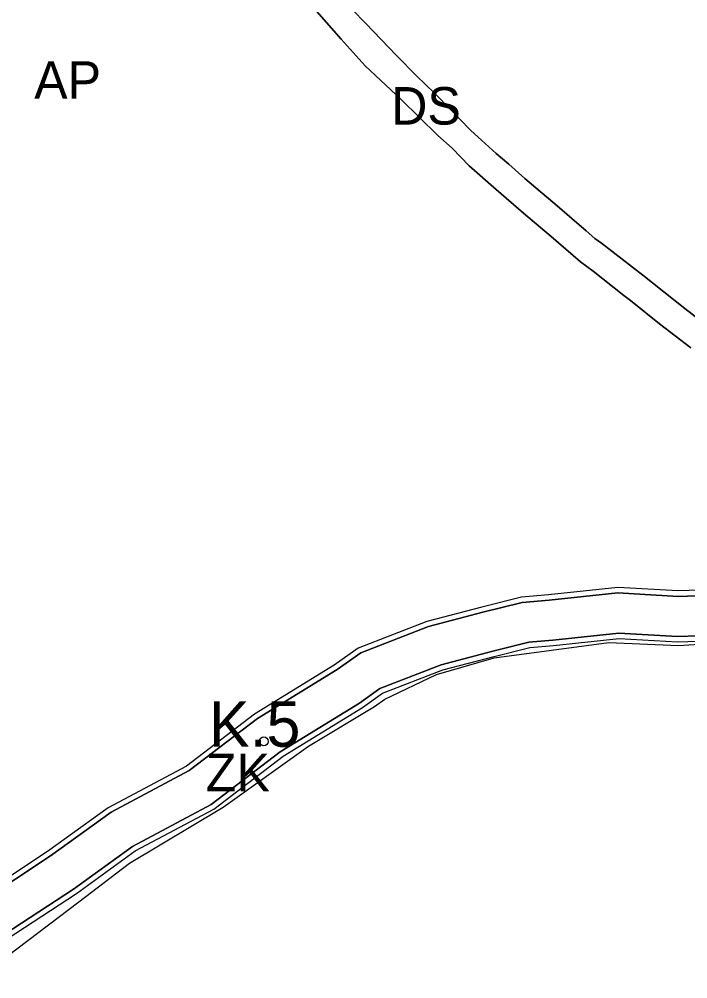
# Model space of a CAD drawing. Extents: x -555509 to -553005, y -1186756 to -1182560.
# Drawn here: x -553505.6 to -553255.9, y -1186166.6 to -1185808.2 of the extents above; entities that cross this region are included whole.
import ezdxf

# ---------------------------------------------------------------- set-up
doc = ezdxf.new("R2010")
doc.units = 0
for name, color, linetype in [('Level 26', 7, 'Continuous'), ('Level 46', 7, 'Continuous'), ('Level 56', 7, 'Continuous'), ('Level 59', 7, 'Continuous'), ('Level 63', 7, 'Continuous'), ('navrh_ZK', 7, 'Continuous'), ('OBRYS_PLOCH', 7, 'Continuous'), ('stav_AP', 7, 'Continuous'), ('stav_DS', 7, 'Continuous')]:
    doc.layers.add(name, color=color, linetype=linetype)

msp = doc.modelspace()

# ---------------------------------------------------------------- linework, layer by layer
at = {"layer": 'Level 26'}
for p, q in [((-553306.3, -1186040.1), (-553315.27, -1186040.84)), ((-553281.66, -1186037.48), (-553306.3, -1186040.1)), ((-553259.77, -1186038.75), (-553281.66, -1186037.48)), ((-553237.04, -1186038), (-553259.77, -1186038.75)), ((-553315.27, -1186040.84), (-553328.68, -1186044.22)), ((-553328.28, -1186046.67), (-553285.47, -1186040.94)), ((-553285.47, -1186040.94), (-553259.44, -1186042.1)), ((-553259.44, -1186042.1), (-553232.89, -1186040.35)), ((-553349.78, -1186052.91), (-553328.28, -1186046.67)), ((-553328.68, -1186044.22), (-553348.08, -1186049.28)), ((-553348.08, -1186049.28), (-553370.87, -1186058.18)), ((-553369.03, -1186062.12), (-553349.78, -1186052.91)), ((-553370.87, -1186058.18), (-553378.55, -1186063.63)), ((-553378.55, -1186063.63), (-553408.08, -1186081.8)), ((-553397.54, -1186079.66), (-553372.88, -1186064.84)), ((-553372.88, -1186064.84), (-553369.03, -1186062.12)), ((-553429.45, -1186102.43), (-553397.54, -1186079.66)), ((-553408.08, -1186081.8), (-553433.95, -1186101.46)), ((-553464.42, -1186123.36), (-553429.45, -1186102.43)), ((-553433.95, -1186101.46), (-553463.3, -1186117.12)), ((-553463.3, -1186117.12), (-553485.32, -1186133.04)), ((-553483.34, -1186137.78), (-553464.42, -1186123.36)), ((-553485.32, -1186133.04), (-553511.19, -1186150.03)), ((-553521.16, -1186166.55), (-553483.34, -1186137.78))]:
    msp.add_line(p, q, dxfattribs=at)
at = {"layer": 'Level 46'}
msp.add_circle((-553414.23, -1186077.88), 1.64, dxfattribs=at)
at = {"layer": 'Level 56'}
for points in [[(-553239.12, -1186021.06), (-553259.56, -1186021.73), (-553282.07, -1186020.43), (-553307.9, -1186023.17), (-553318.06, -1186024.01), (-553332.9, -1186027.75), (-553353.34, -1186033.08), (-553379, -1186043.11), (-553387.93, -1186049.44), (-553417.7, -1186067.76), (-553443.15, -1186087.1), (-553472.32, -1186102.67), (-553494.97, -1186119.04), (-553521, -1186136.13)], [(-553510.04, -1186151.66), (-553484.18, -1186134.69), (-553462.24, -1186118.82), (-553432.87, -1186103.15), (-553406.95, -1186083.45), (-553377.45, -1186065.3), (-553369.91, -1186059.95), (-553347.46, -1186051.19), (-553328.18, -1186046.16), (-553314.94, -1186042.82), (-553306.11, -1186042.09), (-553281.61, -1186039.49), (-553259.79, -1186040.75), (-553236.8, -1186039.99)]]:
    msp.add_lwpolyline(points, dxfattribs=at)
at = {"layer": 'navrh_ZK'}
for points in [[(-553238.87, -1186023.05), (-553259.58, -1186023.74), (-553282.02, -1186022.43), (-553307.71, -1186025.17), (-553317.74, -1186025.99), (-553332.41, -1186029.69), (-553352.72, -1186034.99), (-553378.05, -1186044.88), (-553386.83, -1186051.11), (-553416.57, -1186069.41), (-553442.07, -1186088.79), (-553471.26, -1186104.37), (-553493.84, -1186120.69), (-553519.85, -1186137.77)], [(-553511.19, -1186150.03), (-553485.32, -1186133.04), (-553463.3, -1186117.12), (-553433.95, -1186101.46), (-553408.08, -1186081.8), (-553378.55, -1186063.63), (-553370.87, -1186058.18), (-553348.08, -1186049.28), (-553328.68, -1186044.22), (-553315.27, -1186040.84), (-553306.3, -1186040.1), (-553281.66, -1186037.48), (-553259.77, -1186038.75), (-553237.04, -1186038)]]:
    msp.add_lwpolyline(points, dxfattribs=at)
at = {"layer": 'OBRYS_PLOCH'}
for p, q in [((-553402.77, -1185795.87), (-553385.33, -1185815.75)), ((-553385.33, -1185815.75), (-553402.77, -1185795.87)), ((-553385.33, -1185815.75), (-553402.77, -1185795.87)), ((-553381.11, -1185804.72), (-553376.26, -1185809.74)), ((-553376.26, -1185809.74), (-553381.11, -1185804.72)), ((-553376.26, -1185809.74), (-553370.42, -1185815.8)), ((-553370.42, -1185815.8), (-553376.26, -1185809.74)), ((-553385.33, -1185815.75), (-553376.38, -1185825.65)), ((-553376.38, -1185825.65), (-553385.33, -1185815.75)), ((-553376.38, -1185825.65), (-553385.33, -1185815.75)), ((-553370.42, -1185815.8), (-553364.57, -1185821.89)), ((-553364.57, -1185821.89), (-553370.42, -1185815.8)), ((-553364.57, -1185821.89), (-553357.23, -1185829.41)), ((-553357.23, -1185829.41), (-553364.57, -1185821.89)), ((-553376.38, -1185825.65), (-553362.96, -1185838.27)), ((-553362.96, -1185838.27), (-553376.38, -1185825.65)), ((-553362.96, -1185838.27), (-553376.38, -1185825.65)), ((-553357.23, -1185829.41), (-553350.57, -1185835.89)), ((-553350.57, -1185835.89), (-553357.23, -1185829.41)), ((-553350.57, -1185835.89), (-553344.21, -1185842.36)), ((-553344.21, -1185842.36), (-553350.57, -1185835.89)), ((-553362.96, -1185838.27), (-553349.22, -1185851.67)), ((-553349.22, -1185851.67), (-553362.96, -1185838.27)), ((-553349.22, -1185851.67), (-553362.96, -1185838.27)), ((-553344.21, -1185842.36), (-553337.49, -1185849.32)), ((-553337.49, -1185849.32), (-553344.21, -1185842.36)), ((-553337.49, -1185849.32), (-553337.01, -1185849.82)), ((-553337.01, -1185849.82), (-553337.49, -1185849.32)), ((-553337.01, -1185849.82), (-553332.98, -1185853.45)), ((-553332.98, -1185853.45), (-553337.01, -1185849.82)), ((-553349.22, -1185851.67), (-553343.93, -1185856.35)), ((-553343.93, -1185856.35), (-553349.22, -1185851.67)), ((-553343.93, -1185856.35), (-553349.22, -1185851.67)), ((-553332.98, -1185853.45), (-553327.51, -1185858.37)), ((-553327.51, -1185858.37), (-553332.98, -1185853.45)), ((-553343.93, -1185856.35), (-553337.6, -1185862.96)), ((-553337.6, -1185862.96), (-553343.93, -1185856.35)), ((-553337.6, -1185862.96), (-553343.93, -1185856.35)), ((-553327.51, -1185858.37), (-553322.77, -1185862.39)), ((-553322.77, -1185862.39), (-553327.51, -1185858.37)), ((-553337.6, -1185862.96), (-553327.44, -1185871.78)), ((-553327.44, -1185871.78), (-553337.6, -1185862.96)), ((-553327.44, -1185871.78), (-553337.6, -1185862.96)), ((-553322.77, -1185862.39), (-553316.74, -1185867.67)), ((-553316.74, -1185867.67), (-553322.77, -1185862.39)), ((-553316.74, -1185867.67), (-553311.01, -1185872.54)), ((-553311.01, -1185872.54), (-553316.74, -1185867.67)), ((-553327.44, -1185871.78), (-553317.23, -1185880.63)), ((-553317.23, -1185880.63), (-553327.44, -1185871.78)), ((-553317.23, -1185880.63), (-553327.44, -1185871.78)), ((-553311.01, -1185872.54), (-553305.6, -1185877.13)), ((-553305.6, -1185877.13), (-553311.01, -1185872.54)), ((-553305.6, -1185877.13), (-553299.29, -1185882.62)), ((-553299.29, -1185882.62), (-553305.6, -1185877.13)), ((-553317.23, -1185880.63), (-553306.92, -1185889.37)), ((-553306.92, -1185889.37), (-553317.23, -1185880.63)), ((-553306.92, -1185889.37), (-553317.23, -1185880.63)), ((-553299.29, -1185882.62), (-553293.85, -1185887.3)), ((-553293.85, -1185887.3), (-553299.29, -1185882.62)), ((-553306.92, -1185889.37), (-553295.97, -1185898.84)), ((-553295.97, -1185898.84), (-553306.92, -1185889.37)), ((-553295.97, -1185898.84), (-553306.92, -1185889.37)), ((-553293.85, -1185887.3), (-553290.71, -1185890.11)), ((-553290.71, -1185890.11), (-553293.85, -1185887.3)), ((-553290.71, -1185890.11), (-553288.2, -1185891.84)), ((-553288.2, -1185891.84), (-553290.71, -1185890.11)), ((-553288.2, -1185891.84), (-553272.75, -1185903.87)), ((-553272.75, -1185903.87), (-553288.2, -1185891.84)), ((-553295.97, -1185898.84), (-553291.3, -1185902.33)), ((-553291.3, -1185902.33), (-553295.97, -1185898.84)), ((-553291.3, -1185902.33), (-553295.97, -1185898.84)), ((-553291.3, -1185902.33), (-553279.88, -1185911.4)), ((-553279.88, -1185911.4), (-553291.3, -1185902.33)), ((-553279.88, -1185911.4), (-553291.3, -1185902.33)), ((-553272.75, -1185903.87), (-553257.04, -1185916.2)), ((-553257.04, -1185916.2), (-553272.75, -1185903.87)), ((-553279.88, -1185911.4), (-553277.29, -1185913.25)), ((-553277.29, -1185913.25), (-553279.88, -1185911.4)), ((-553277.29, -1185913.25), (-553279.88, -1185911.4)), ((-553277.29, -1185913.25), (-553266.45, -1185922.03)), ((-553266.45, -1185922.03), (-553277.29, -1185913.25)), ((-553266.45, -1185922.03), (-553277.29, -1185913.25)), ((-553257.04, -1185916.2), (-553241.32, -1185928.48)), ((-553241.32, -1185928.48), (-553257.04, -1185916.2)), ((-553266.45, -1185922.03), (-553254.85, -1185930.89)), ((-553254.85, -1185930.89), (-553266.45, -1185922.03)), ((-553254.85, -1185930.89), (-553266.45, -1185922.03)), ((-553317.74, -1186025.99), (-553307.71, -1186025.17)), ((-553307.71, -1186025.17), (-553282.02, -1186022.43)), ((-553282.02, -1186022.43), (-553259.58, -1186023.74)), ((-553259.58, -1186023.74), (-553238.87, -1186023.05)), ((-553378.05, -1186044.88), (-553352.72, -1186034.99)), ((-553306.3, -1186040.1), (-553315.27, -1186040.84)), ((-553281.66, -1186037.48), (-553306.3, -1186040.1)), ((-553259.77, -1186038.75), (-553281.66, -1186037.48)), ((-553237.04, -1186038), (-553259.77, -1186038.75)), ((-553315.27, -1186040.84), (-553328.68, -1186044.22)), ((-553328.28, -1186046.67), (-553285.47, -1186040.94)), ((-553285.47, -1186040.94), (-553259.44, -1186042.1)), ((-553259.44, -1186042.1), (-553232.89, -1186040.35)), ((-553386.83, -1186051.11), (-553378.05, -1186044.88)), ((-553349.78, -1186052.91), (-553328.28, -1186046.67)), ((-553328.68, -1186044.22), (-553348.08, -1186049.28)), ((-553348.08, -1186049.28), (-553370.87, -1186058.18)), ((-553416.57, -1186069.41), (-553386.83, -1186051.11)), ((-553369.03, -1186062.12), (-553349.78, -1186052.91)), ((-553370.87, -1186058.18), (-553378.55, -1186063.63)), ((-553378.55, -1186063.63), (-553408.08, -1186081.8)), ((-553397.54, -1186079.66), (-553372.88, -1186064.84)), ((-553372.88, -1186064.84), (-553369.03, -1186062.12)), ((-553429.45, -1186102.43), (-553397.54, -1186079.66)), ((-553408.08, -1186081.8), (-553433.95, -1186101.46)), ((-553471.26, -1186104.37), (-553442.07, -1186088.79)), ((-553493.84, -1186120.69), (-553471.26, -1186104.37)), ((-553464.42, -1186123.36), (-553429.45, -1186102.43)), ((-553433.95, -1186101.46), (-553463.3, -1186117.12)), ((-553463.3, -1186117.12), (-553485.32, -1186133.04)), ((-553519.85, -1186137.77), (-553493.84, -1186120.69)), ((-553483.34, -1186137.78), (-553464.42, -1186123.36)), ((-553485.32, -1186133.04), (-553511.19, -1186150.03)), ((-553521.16, -1186166.55), (-553483.34, -1186137.78))]:
    msp.add_line(p, q, dxfattribs=at)
for points in [[(-553307.71, -1186025.17), (-553282.02, -1186022.43), (-553259.58, -1186023.74), (-553238.87, -1186023.05), (-553235.04, -1186022.23), (-553222.52, -1186019.49)], [(-553238.87, -1186023.05), (-553259.58, -1186023.74), (-553282.02, -1186022.43), (-553307.71, -1186025.17), (-553317.74, -1186025.99), (-553332.41, -1186029.69), (-553352.72, -1186034.99), (-553378.05, -1186044.88), (-553386.83, -1186051.11), (-553416.57, -1186069.41), (-553442.07, -1186088.79), (-553471.26, -1186104.37), (-553493.84, -1186120.69), (-553519.85, -1186137.77)], [(-553332.41, -1186029.69), (-553317.74, -1186025.99), (-553307.71, -1186025.17)], [(-553352.72, -1186034.99), (-553332.41, -1186029.69), (-553317.74, -1186025.99)], [(-553378.05, -1186044.88), (-553352.72, -1186034.99), (-553332.41, -1186029.69)], [(-553511.19, -1186150.03), (-553485.32, -1186133.04), (-553463.3, -1186117.12), (-553433.95, -1186101.46), (-553408.08, -1186081.8), (-553378.55, -1186063.63), (-553370.87, -1186058.18), (-553348.08, -1186049.28), (-553328.68, -1186044.22), (-553315.27, -1186040.84), (-553306.3, -1186040.1), (-553281.66, -1186037.48), (-553259.77, -1186038.75), (-553237.04, -1186038)], [(-553442.07, -1186088.79), (-553416.57, -1186069.41), (-553386.83, -1186051.11), (-553378.05, -1186044.88)], [(-553535.86, -1186150.36), (-553531.2, -1186146.37), (-553519.85, -1186137.77), (-553493.84, -1186120.69), (-553471.26, -1186104.37), (-553442.07, -1186088.79), (-553416.57, -1186069.41)]]:
    msp.add_lwpolyline(points, dxfattribs=at)
at = {"layer": 'stav_AP'}
for p, q in [((-553385.33, -1185815.75), (-553402.77, -1185795.87)), ((-553381.11, -1185804.72), (-553376.26, -1185809.74)), ((-553376.26, -1185809.74), (-553370.42, -1185815.8)), ((-553376.38, -1185825.65), (-553385.33, -1185815.75)), ((-553370.42, -1185815.8), (-553364.57, -1185821.89)), ((-553364.57, -1185821.89), (-553357.23, -1185829.41)), ((-553362.96, -1185838.27), (-553376.38, -1185825.65)), ((-553357.23, -1185829.41), (-553350.57, -1185835.89)), ((-553350.57, -1185835.89), (-553344.21, -1185842.36)), ((-553349.22, -1185851.67), (-553362.96, -1185838.27)), ((-553344.21, -1185842.36), (-553337.49, -1185849.32)), ((-553337.49, -1185849.32), (-553337.01, -1185849.82)), ((-553337.01, -1185849.82), (-553332.98, -1185853.45)), ((-553343.93, -1185856.35), (-553349.22, -1185851.67)), ((-553332.98, -1185853.45), (-553327.51, -1185858.37)), ((-553337.6, -1185862.96), (-553343.93, -1185856.35)), ((-553327.51, -1185858.37), (-553322.77, -1185862.39)), ((-553327.44, -1185871.78), (-553337.6, -1185862.96)), ((-553322.77, -1185862.39), (-553316.74, -1185867.67)), ((-553316.74, -1185867.67), (-553311.01, -1185872.54)), ((-553317.23, -1185880.63), (-553327.44, -1185871.78)), ((-553311.01, -1185872.54), (-553305.6, -1185877.13)), ((-553305.6, -1185877.13), (-553299.29, -1185882.62)), ((-553306.92, -1185889.37), (-553317.23, -1185880.63)), ((-553299.29, -1185882.62), (-553293.85, -1185887.3)), ((-553295.97, -1185898.84), (-553306.92, -1185889.37)), ((-553293.85, -1185887.3), (-553290.71, -1185890.11)), ((-553290.71, -1185890.11), (-553288.2, -1185891.84)), ((-553288.2, -1185891.84), (-553272.75, -1185903.87)), ((-553291.3, -1185902.33), (-553295.97, -1185898.84)), ((-553279.88, -1185911.4), (-553291.3, -1185902.33)), ((-553272.75, -1185903.87), (-553257.04, -1185916.2)), ((-553277.29, -1185913.25), (-553279.88, -1185911.4)), ((-553266.45, -1185922.03), (-553277.29, -1185913.25)), ((-553257.04, -1185916.2), (-553241.32, -1185928.48)), ((-553254.85, -1185930.89), (-553266.45, -1185922.03)), ((-553317.74, -1186025.99), (-553307.71, -1186025.17)), ((-553259.58, -1186023.74), (-553238.87, -1186023.05)), ((-553378.05, -1186044.88), (-553352.72, -1186034.99)), ((-553442.07, -1186088.79), (-553416.57, -1186069.41)), ((-553519.85, -1186137.77), (-553493.84, -1186120.69))]:
    msp.add_line(p, q, dxfattribs=at)
for points in [[(-553307.71, -1186025.17), (-553282.02, -1186022.43), (-553259.58, -1186023.74)], [(-553352.72, -1186034.99), (-553332.41, -1186029.69), (-553317.74, -1186025.99)], [(-553416.57, -1186069.41), (-553386.83, -1186051.11), (-553378.05, -1186044.88)], [(-553493.84, -1186120.69), (-553471.26, -1186104.37), (-553442.07, -1186088.79)]]:
    msp.add_lwpolyline(points, dxfattribs=at)
at = {"layer": 'stav_DS'}
for p, q in [((-553402.77, -1185795.87), (-553385.33, -1185815.75)), ((-553376.26, -1185809.74), (-553381.11, -1185804.72)), ((-553370.42, -1185815.8), (-553376.26, -1185809.74)), ((-553385.33, -1185815.75), (-553376.38, -1185825.65)), ((-553364.57, -1185821.89), (-553370.42, -1185815.8)), ((-553357.23, -1185829.41), (-553364.57, -1185821.89)), ((-553376.38, -1185825.65), (-553362.96, -1185838.27)), ((-553350.57, -1185835.89), (-553357.23, -1185829.41)), ((-553344.21, -1185842.36), (-553350.57, -1185835.89)), ((-553362.96, -1185838.27), (-553349.22, -1185851.67)), ((-553337.49, -1185849.32), (-553344.21, -1185842.36)), ((-553337.01, -1185849.82), (-553337.49, -1185849.32)), ((-553332.98, -1185853.45), (-553337.01, -1185849.82)), ((-553349.22, -1185851.67), (-553343.93, -1185856.35)), ((-553327.51, -1185858.37), (-553332.98, -1185853.45)), ((-553343.93, -1185856.35), (-553337.6, -1185862.96)), ((-553322.77, -1185862.39), (-553327.51, -1185858.37)), ((-553337.6, -1185862.96), (-553327.44, -1185871.78)), ((-553316.74, -1185867.67), (-553322.77, -1185862.39)), ((-553311.01, -1185872.54), (-553316.74, -1185867.67)), ((-553327.44, -1185871.78), (-553317.23, -1185880.63)), ((-553305.6, -1185877.13), (-553311.01, -1185872.54)), ((-553299.29, -1185882.62), (-553305.6, -1185877.13)), ((-553317.23, -1185880.63), (-553306.92, -1185889.37)), ((-553293.85, -1185887.3), (-553299.29, -1185882.62)), ((-553306.92, -1185889.37), (-553295.97, -1185898.84)), ((-553290.71, -1185890.11), (-553293.85, -1185887.3)), ((-553288.2, -1185891.84), (-553290.71, -1185890.11)), ((-553272.75, -1185903.87), (-553288.2, -1185891.84)), ((-553295.97, -1185898.84), (-553291.3, -1185902.33)), ((-553291.3, -1185902.33), (-553279.88, -1185911.4)), ((-553257.04, -1185916.2), (-553272.75, -1185903.87)), ((-553279.88, -1185911.4), (-553277.29, -1185913.25)), ((-553277.29, -1185913.25), (-553266.45, -1185922.03)), ((-553241.32, -1185928.48), (-553257.04, -1185916.2)), ((-553266.45, -1185922.03), (-553254.85, -1185930.89))]:
    msp.add_line(p, q, dxfattribs=at)

# ---------------------------------------------------------------- texts
at = {"layer": 'Level 46'}
msp.add_text('K.5', height=17, dxfattribs=at).set_placement((-553434.69, -1186079.9))
at = {"layer": 'Level 59'}
for s, p in [('AP', (-553499.97, -1185837.96)), ('DS', (-553366.68, -1185847.59))]:
    msp.add_text(s, height=14, dxfattribs=at).set_placement(p)
at = {"layer": 'Level 63'}
msp.add_text('ZK', height=14, dxfattribs=at).set_placement((-553435.91, -1186096.54))

doc.saveas('drawing.dxf')
